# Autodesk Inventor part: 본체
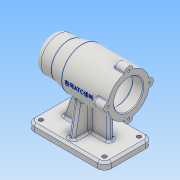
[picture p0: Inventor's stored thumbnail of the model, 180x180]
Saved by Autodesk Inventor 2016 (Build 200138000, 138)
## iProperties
Created: 2019-07
Part Number: 본체
Material: 알루미늄 6061
Document SubType Name: Modeling
Designer: 3sil_cad0123
Density: 2.7 g/cm^3
Appearance: 알루미늄 - 평지
Mass: 644.247 g
Surface Area: 655.732 cm^2
Volume: 238.61 cm^3
Author: 3sil_cad0123
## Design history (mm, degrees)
sketch "스케치1"
  geometry: 1 further point
sketch "스케치2"
  geometry: L1 (0, 0)-(0, 30); L2 (0, 30)-(-67, 30); L3 (-67, 30)-(-87, 25); L4 (-87, 25)-(-102, 25); L5 (-112, 15)-(-112, 0); L6 (-112, 0)-(0, 0); A1 r 10 centre (-102, 15) between (-102, 25) and (-112, 15); 1 further point
  constraints: 12 end point, 3 perpendicular, 2 point on circle, 2 point on line, 2 tangent, 1 centre point, 1 parallel, 1 vertical
  dimensions: "d0" = 112 distance between parallel lines of L1 L5; "d1" = 45 distance from line of L2.end L5; "d2" = 25 distance of L3.end point (-112, 25); "d3" = 60 diameter of L2 L6; "d4" = 50 diameter of L4 L6; "d5" = 10 radius of A1
revolve "회전1" sketch "스케치2" stored, may be unused: angle "d6" = 90 deg
sketch "스케치3"
  geometry: L1 (0, 0)-(-15, 0); L2 (-15, 0)-(-15, 21); L3 (-15, 21)-(0, 21); L4 (0, 21)-(0, 0); L5 (-15, 0)-(-69, 0); L6 (-69, 0)-(-69, 21); L7 (-66, 24)-(-18, 24); L8 (-15, 21)-(-15, 0); L9 (-69, 0)-(-81, 0); L10 (-81, 0)-(-81, 20.7); L11 (-80.7, 21)-(-69, 21); L12 (-69, 21)-(-69, 0); L13 (-81, 0)-(-99, 0); L14 (-99, 0)-(-99, 17.2); L15 (-98.7, 17.5)-(-81, 17.5); L16 (-81, 17.5)-(-81, 0); L17 (-99, 0)-(-103, 0); L18 (-103, 0)-(-103, 15.7); L19 (-102.7, 16)-(-99, 16); L20 (-99, 16)-(-99, 0); L21 (-103, 0)-(-106, 0); L22 (-106, 0)-(-106, 10.5); L23 (-106, 10.5)-(-103, 10.5); L24 (-103, 10.5)-(-103, 0); A1 r 0.3 centre (-80.7, 20.7) between (-80.7, 21) and (-81, 20.7); A2 r 0.3 centre (-98.7, 17.2) between (-98.7, 17.5) and (-99, 17.2); A3 r 0.3 centre (-102.7, 15.7) between (-102.7, 16) and (-103, 15.7); A4 r 3 centre (-66, 21) between (-66, 24) and (-69, 21); A5 r 3 centre (-18, 21) between (-15, 21) and (-18, 24); 5 further points
  constraints: 48 end point, 12 parallel, 10 point on circle, 10 point on line, 10 tangent, 6 horizontal, 6 perpendicular, 5 centre point, 3 equal radius
  dimensions: "d9" = 21 distance between parallel lines of L9 L11; "d10" = 17.5 distance between parallel lines of L13 L15; "d11" = 16 distance between parallel lines of L17 L19; "d12" = 10.5 distance between parallel lines of L21 L23; "d13" = 15 distance of L2.end L3.end; "d14" = 24 distance between parallel lines of L5 L7; "d15" = 21 distance between parallel lines of L1 L3; "d16" = 54 distance of point (-69, 24) point (-15, 24); "d17" = 12 distance of point (-81, 21) L11.end; "d18" = 18 distance of point (-99, 17.5) L15.end; "d19" = 4 distance of point (-103, 16) L19.end; "d20" = 3 distance of L22.end L23.end; "d21" = 0.3 radius of A1; "d22" = 3 radius of A4
revolve "회전2" sketch "스케치3" stored, may be unused: angle "d23" = 90 deg
sketch "스케치4"
  geometry: C1 r 21 at (0, 0) reference; C2 r 6 at (0, 30); C3 r 6 at (-30, 0); C4 r 6 at (0, -30); C5 r 6 at (30, 0); 1 further point
  constraints: 4 centre point, 1 vertical alignment, 10 other
  dimensions: "d26" = 360 deg dimension on C1.centre C2.centre (derived)
extrude "돌출1" join sketch "스케치4" distance "d28" = 16; taper "d29" = 0 deg
sketch "스케치5"
  geometry: A1 r 6 centre (30, 30) between (35.97, 29.4) and (24.03, 29.4) reference; A2 r 6 centre (0, 0) between (0.6, 5.97) and (0.6, -5.97) reference; A3 r 6 centre (30, -30) between (24.03, -29.4) and (35.97, -29.4) reference; A4 r 6 centre (60, 0) between (59.4, -5.97) and (59.4, 5.97) reference
hole "구멍1" sketch "스케치5" at (60, 0), (30, -30), (0, 0), (30, 30) diameter "d30" = 3.242; stored, may be unused: countersink angle "d34" = 90 deg, drill point angle "d36" = 118 deg; dims "d31" = 8, "d32" = 4, "d33" = 2, "d35" = 11
fillet "모깎기1" dims "d37" = 3
fillet "모깎기2" dims "d38" = 1
node "작업 평면1"
sketch "스케치6"
  geometry: L1 (0, -35)-(112, -35); L2 (112, -35)-(112, 35); L3 (112, 35)-(0, 35); L4 (0, 35)-(0, -35); 2 further points
  constraints: 8 end point, 2 parallel, 1 coincident, 1 horizontal, 1 midpoint, 1 perpendicular
  dimensions: "d40" = 112 distance of L2.end L3.end; "d41" = 70 distance of L1.end L2.end
extrude "돌출2" join sketch "스케치6" distance "d42" = 10; taper "d43" = 0 deg
fillet "모깎기3" dims "d44" = 10
sketch "스케치7"
  geometry: A1 r 10 centre (102, -25) between (102, -35) and (112, -25) reference; A2 r 10 centre (102, 25) between (112, 25) and (102, 35) reference; A3 r 10 centre (10, 25) between (10, 35) and (0, 25) reference; A4 r 10 centre (10, -25) between (0, -25) and (10, -35) reference; 1 further point
hole "구멍2" sketch "스케치7" at (10, 25), (10, -25), (102, -25), (102, 25) diameter "d45" = 6; stored, may be unused: countersink angle "d49" = 90 deg, drill point angle "d51" = 118 deg; dims "d46" = 8, "d47" = 4, "d48" = 2, "d50" = 11
node "작업 평면2"
sketch "스케치8"
  geometry: L1 (0, 6.771)-(0, 29.226) reference; 2 further points
  constraints: 1 horizontal alignment, 1 other
  dimensions: "d53" = 42 distance from line of L1 point (-42, 0)
feature "엠보싱1" sketch "스케치8" dims "d0" = 112, "d1" = 45, "d2" = 25, "d3" = 60, "d4" = 50, "d5" = 10, "d9" = 21, "d10" = 17.5, "d11" = 16, "d12" = 10.5, "d13" = 15, "d14" = 24, "d15" = 21, "d16" = 54, "d17" = 12, "d18" = 18, "d19" = 4, "d20" = 3, "d21" = 0.3, "d22" = 3, "d54" = 0.5, "d55" = 0
node "작업 평면3"
sketch "스케치10"
  geometry: L1 (-35, -70)-(-25, -70) reference; L2 (-28, -70)-(-19.207, -20.133); L3 (19.206, -20.126)-(28, -70); L4 (25, -70)-(35, -70) reference; L5 (-28, -70)-(28, -70); L6 (-35, -80)-(-35, -70) reference; L7 (35, -70)-(35, -80) reference; L8 (-19.207, -20.133)-(-5.193, -26.929); L9 (-5.193, -26.929)-(5.853, -26.929); L10 (5.853, -26.929)-(19.206, -20.126); 1 further point
  constraints: 12 end point, 2 point on line, 1 collinear, 1 horizontal
  dimensions: "d61" = 7 distance from line of L2.start L6; "d62" = 7 distance from line of L3.end L7; "d63" = 100 deg angle of L3 L4; "d64" = 100 deg angle of L1 L2
extrude "돌출3" join sketch "스케치10" stored distance "d65" = 8; taper "d66" = 0 deg
sketch "스케치11"
  geometry: L1 (-10, -70)-(-102, -70) reference; L2 (-92, -70)-(-83.173, -45.749); L3 (-112, -80)-(-112, -70) reference; 1 further point
  constraints: 2 end point, 1 point on line
  dimensions: "d67" = 20 distance from line of L3 L2.start; "d68" = 110 deg angle of L1 L2
feature "리브1" sketch "스케치11" dims "d69" = 1, "d70" = 8, "d71" = 0, "d72" = 0, "d73" = 1, "d74" = 1
sketch "스케치13"
  geometry: L1 (0, 25)-(0, -25) reference; L2 (52, -28)-(52, 28) reference; L3 (25, -4)-(52, -4); L4 (52, -4)-(52, 4); L5 (52, 4)-(25, 4); L6 (25, 4)-(25, -4); L7 (25, -4)-(52, 4); L8 (52, -4)-(25, 4); 4 further points
  constraints: 12 end point, 4 midpoint, 2 parallel, 1 horizontal, 1 horizontal alignment, 1 perpendicular, 1 point on line
  dimensions: "d75" = 25 distance between parallel lines of L6 L1; "d76" = 8 distance of L5.end L3.start
extrude "돌출4" join sketch "스케치13" stored distance "d77" = 8; taper "d78" = 0 deg
fillet "모깎기4" dims "d79" = 3
fillet "모깎기5" dims "d80" = 3
chamfer "모따기1" distance "d82" = 3; stored, may be unused: second distance "d83" = 2, angle "d84" = 45 deg
fillet "모깎기7" dims "d85" = 3
fillet "모깎기8" dims "d86" = 3
chamfer "모따기2" distance "d87" = 1; stored, may be unused: second distance "d88" = 2, angle "d89" = 45 deg
node "솔리드1"
other parameters: "d52" = 44.75, "d60" = 56
